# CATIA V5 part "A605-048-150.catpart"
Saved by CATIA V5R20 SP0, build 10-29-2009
Part number: A605-048-150
Source: Unknown
Property "A": "0.000"
Property "ARTICLENO": "A605-048-150"
Property "BOMINFO": "A605-048-150"
Property "CODE": "A605-048-150"
Property "D": "9.000"
Property "FORM": "B"
Property "L": "150.000"
Property "L1": "60.000"
Property "LINA": "A605-048-150"
Property "NB": "A605-048-150"
Property "NBSYN": "$CODE."
Property "NN": "A605"
Property "NT": "Wear Plates, self-lubricating"
Property "SCREW": "3*M8X16"
Property "SUPPLIER": "CF"
Property "W": "48.000"
Bounding box of the stored display mesh (mm): x -48 to 0, y 0 to 5, z -150 to 0
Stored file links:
  C:\Users\Utente\Desktop\3D files A605\A605-048-150.catpart
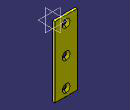
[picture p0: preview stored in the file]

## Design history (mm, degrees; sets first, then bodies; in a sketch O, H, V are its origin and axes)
Body1 "Geometry.1" (main body)
  Solid1 "A605-048-150.catpart": solid without history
